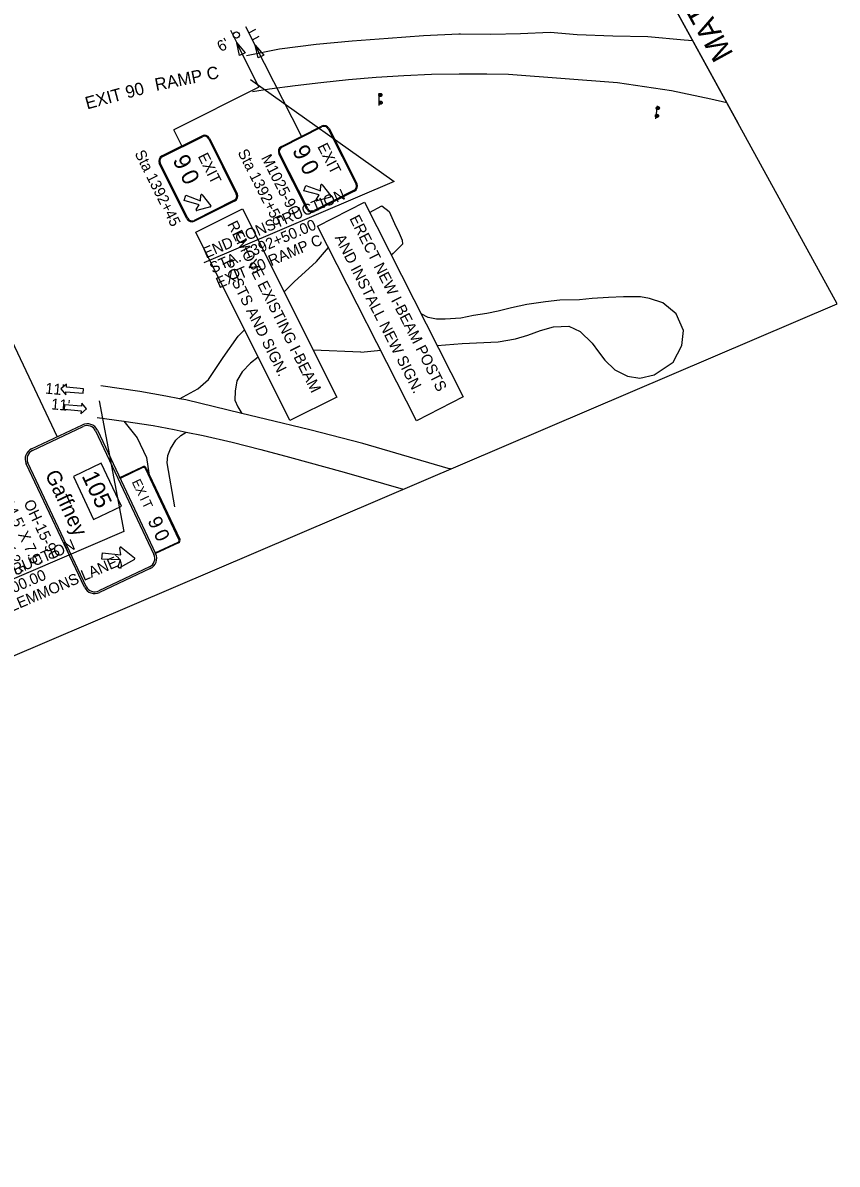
# Model space of a CAD drawing. Extents: x 1786955 to 1788674, y 1181944 to 1183335.
# Drawn here: x 1788151 to 1788674, y 1181944 to 1182676 of the extents above; entities that cross this region are included whole.
import ezdxf

# ---------------------------------------------------------------- set-up
doc = ezdxf.new("R2010")
doc.units = 0
for name, color, linetype in [('RD_EX_Road', 7, 'Continuous'), ('RD_PD_Final_LnLine', 7, 'Continuous'), ('RD_PD_Final_TX', 7, 'Continuous'), ('RD_SHT_MatchLine', 7, 'Continuous'), ('RD_SHT_ShtClip', 7, 'Continuous'), ('RD_TX_RoadID', 7, 'Continuous'), ('SN_P_Signs', 7, 'Continuous')]:
    doc.layers.add(name, color=color, linetype=linetype)

# ---------------------------------------------------------------- blocks, each defined once
blk = doc.blocks.new('SARRW2')
at = {"layer": 'RD_PD_Final_LnLine'}
blk.add_lwpolyline([(-12, 1.2), (-12, -1.2), (-2.83, -1.2), (-2.83, -2.83), (0, 0), (-2.83, 2.83), (-2.83, 1.2)], close=True, dxfattribs=at)

msp = doc.modelspace()

# ---------------------------------------------------------------- linework, layer by layer
at = {"layer": 'RD_EX_Road'}
for points in [[(1788294.76, 1182655.02), (1788315.9, 1182659.32), (1788339.4, 1182662.27), (1788362.48, 1182664.45), (1788385.58, 1182666.23), (1788408.27, 1182667.76), (1788430.98, 1182668.89), (1788431.91, 1182668.93), (1788451.42, 1182668.77), (1788470.57, 1182669.15), (1788489.45, 1182669.9), (1788506.9, 1182668.61), (1788529.76, 1182667.55), (1788552.17, 1182667.13), (1788575.33, 1182665.19), (1788580.91, 1182664.65)], [(1788602.87, 1182624.63), (1788592.5, 1182626.99), (1788567.37, 1182632.3), (1788532.65, 1182637.51), (1788462.82, 1182642.76), (1788448.94, 1182643.08), (1788431.15, 1182643.12), (1788413.36, 1182642.78), (1788395.59, 1182642.04), (1788377.83, 1182640.9), (1788360.11, 1182639.37), (1788342.42, 1182637.45), (1788325.9, 1182635.62), (1788309.42, 1182633.39), (1788298.64, 1182631.68)], [(1788373.65, 1182554.42), (1788381.55, 1182558.7), (1788386.15, 1182555.09), (1788389.74, 1182547.23), (1788392.6, 1182541.2), (1788394.62, 1182536.61), (1788394.77, 1182534.13), (1788388.76, 1182528.14), (1788387.6, 1182526.96)], [(1788318.89, 1182503.49), (1788325.33, 1182509.81), (1788339.58, 1182522.89), (1788347.43, 1182531.8)], [(1788417, 1182469.07), (1788433.11, 1182470.27), (1788456.25, 1182471.37), (1788467.37, 1182473.39), (1788475.12, 1182475.6), (1788483.32, 1182478.73), (1788491.72, 1182480.94), (1788501.54, 1182481.47), (1788508.68, 1182478.12), (1788516.34, 1182470.51), (1788520.52, 1182464.99), (1788524.48, 1182459.64), (1788530.91, 1182453.4), (1788539.19, 1182449.45), (1788547, 1182448.11), (1788556.13, 1182450.18), (1788568.3, 1182458.45), (1788574, 1182469.06), (1788575.05, 1182478.6), (1788570.41, 1182489.42), (1788561.73, 1182496.5), (1788553.15, 1182499.13), (1788547.45, 1182500.29), (1788536.58, 1182500.34), (1788527.01, 1182499.89), (1788516.38, 1182499.14), (1788508.28, 1182498.39), (1788495.71, 1182498.03), (1788486.45, 1182497.14), (1788474.59, 1182495.26), (1788464.73, 1182493.22), (1788456.24, 1182491.16), (1788448.88, 1182489.64), (1788440.29, 1182488.23), (1788432.15, 1182486.61), (1788422.07, 1182485.89), (1788416.53, 1182485.88), (1788411.21, 1182486.96), (1788406.67, 1182489.4)], [(1788251.81, 1182434.94), (1788263.64, 1182441.16), (1788270.3, 1182447.22), (1788279.89, 1182461.34), (1788289.38, 1182475.08), (1788293.54, 1182479.02)], [(1788302.24, 1182461.59), (1788297.39, 1182457.68), (1788291.96, 1182452.16), (1788288.58, 1182446.33), (1788287.41, 1182439.79), (1788287.23, 1182434.08), (1788289.13, 1182429.7), (1788291.78, 1182425.48)], [(1788368.03, 1182464.82), (1788337.6, 1182466.04)], [(1788368.03, 1182464.82), (1788380.85, 1182466.01)], [(1788425.51, 1182389.86), (1788424.18, 1182390.25), (1788369.44, 1182406.17), (1788335.35, 1182414.95), (1788307.01, 1182421.8), (1788291.78, 1182425.48), (1788255.75, 1182434.17), (1788251.81, 1182434.94), (1788242.95, 1182436.66), (1788226.43, 1182439.52), (1788201.38, 1182443.24)], [(1788198.97, 1182422.96), (1788216.07, 1182420.44), (1788234.94, 1182417.66), (1788248.41, 1182415.12), (1788256.03, 1182413.54), (1788267.02, 1182411.26), (1788285.54, 1182407.02), (1788303.98, 1182402.4), (1788322.31, 1182397.39), (1788357.39, 1182387.74), (1788395.25, 1182376.93)], [(1788216.07, 1182420.44), (1788224.66, 1182409.91), (1788230.53, 1182397.22), (1788232.07, 1182387.1)], [(1788248.9, 1182365.67), (1788243.9, 1182393.83), (1788244.22, 1182398.41), (1788245.93, 1182402.83), (1788249.39, 1182408.32), (1788252.66, 1182411.25), (1788256.03, 1182413.54)]]:
    msp.add_lwpolyline(points, dxfattribs=at)
at = {"layer": 'RD_PD_Final_TX'}
for p, q in [((1788297.3, 1182639.75), (1788389.38, 1182574.31)), ((1788389.38, 1182574.31), (1788267.3, 1182522.14)), ((1788200.24, 1182433.67), (1788216.18, 1182349.73)), ((1788216.18, 1182349.73), (1788094.11, 1182297.56))]:
    msp.add_line(p, q, dxfattribs=at)
at = {"layer": 'RD_SHT_MatchLine'}
msp.add_lwpolyline([(1788610.29, 1182611.12), (1788482.57, 1182843.8), (1788373.62, 1183042.27)], dxfattribs=at)
at = {"layer": 'RD_SHT_ShtClip'}
msp.add_lwpolyline([(1788602.87, 1182624.64), (1788373.62, 1183042.27), (1788169.17, 1183137.08), (1788110.36, 1183228.48), (1786954.94, 1182732.25), (1787147.48, 1182122.09), (1787221.15, 1182060.45), (1787293.74, 1181944.03), (1787901.65, 1182166), (1788673.56, 1182495.86)], close=True, dxfattribs=at)
at = {"layer": 'SN_P_Signs'}
for p, q in [((1788300.31, 1182661.7), (1788294.4, 1182673.33)), ((1788296.27, 1182669.66), (1788300.72, 1182671.92)), ((1788284.48, 1182671.26), (1788288.5, 1182663.21)), ((1788298.54, 1182665.19), (1788302.99, 1182667.45)), ((1788302.77, 1182634.64), (1788288.5, 1182663.21)), ((1788329.99, 1182603.26), (1788300.31, 1182661.7)), ((1788302.77, 1182634.64), (1788248.21, 1182607.38)), ((1788379.88, 1182622.96), (1788379.91, 1182630.78)), ((1788379.91, 1182630.41), (1788381.32, 1182629)), ((1788379.91, 1182629), (1788381.32, 1182630.41)), ((1788380.03, 1182625.51), (1788381.44, 1182624.1)), ((1788380.03, 1182624.1), (1788381.44, 1182625.51)), ((1788557.37, 1182614.44), (1788558.38, 1182622.69)), ((1788557.84, 1182622.01), (1788559.25, 1182620.59)), ((1788557.84, 1182620.59), (1788559.25, 1182622)), ((1788557.25, 1182617.02), (1788558.66, 1182615.6)), ((1788557.25, 1182615.61), (1788558.66, 1182617.02)), ((1788253.35, 1182597.07), (1788248.21, 1182607.38)), ((1788317.15, 1182596.74), (1788342.83, 1182609.78)), ((1788317.43, 1182596.2), (1788343.1, 1182609.25)), ((1788347.14, 1182607.93), (1788365.07, 1182572.62)), ((1788347.67, 1182608.2), (1788365.6, 1182572.89)), ((1788240.47, 1182590.64), (1788266.24, 1182603.51)), ((1788240.74, 1182590.1), (1788266.51, 1182602.97)), ((1788270.53, 1182601.63), (1788288.23, 1182566.2)), ((1788271.07, 1182601.9), (1788288.76, 1182566.47)), ((1788333.51, 1182556.59), (1788315.57, 1182591.9)), ((1788334.04, 1182556.86), (1788316.11, 1182592.17)), ((1788256.56, 1182550.38), (1788238.86, 1182585.81)), ((1788257.09, 1182550.65), (1788239.4, 1182586.08)), ((1788286.88, 1182562.18), (1788261.12, 1182549.31)), ((1788363.75, 1182568.59), (1788338.07, 1182555.55)), ((1788364.02, 1182568.05), (1788338.35, 1182555.01)), ((1788102.41, 1182560.53), (1788173.24, 1182410.52)), ((1788287.15, 1182561.64), (1788261.39, 1182548.77)), ((1788262.23, 1182541.7), (1788292.3, 1182556.72)), ((1788292.3, 1182556.72), (1788352.64, 1182435.93)), ((1788340.39, 1182545.67), (1788370.36, 1182560.9)), ((1788370.36, 1182560.9), (1788433.77, 1182436.06)), ((1788322.56, 1182420.91), (1788262.23, 1182541.7)), ((1788403.8, 1182420.83), (1788340.39, 1182545.67)), ((1788352.64, 1182435.93), (1788322.56, 1182420.91)), ((1788433.77, 1182436.06), (1788403.8, 1182420.83)), ((1788201.51, 1182393.52), (1788183.71, 1182385.11)), ((1788214.53, 1182365.95), (1788201.51, 1182393.52)), ((1788183.71, 1182385.11), (1788196.72, 1182357.55)), ((1788196.72, 1182357.55), (1788214.53, 1182365.95))]:
    msp.add_line(p, q, dxfattribs=at)
for points in [[(1788290.33, 1182654.95), (1788288.5, 1182663.21), (1788294, 1182656.78)], [(1788302.2, 1182653.46), (1788300.31, 1182661.7), (1788305.85, 1182655.32)]]:
    msp.add_lwpolyline(points, close=True, dxfattribs=at)
for points in [[(1788380.62, 1182628.71), (1788380.45, 1182628.72), (1788380.29, 1182628.76), (1788380.14, 1182628.83), (1788380, 1182628.92), (1788379.88, 1182629.04), (1788379.78, 1182629.17), (1788379.7, 1182629.32), (1788379.65, 1182629.48), (1788379.62, 1182629.64), (1788379.62, 1182629.81), (1788379.65, 1182629.97), (1788379.71, 1182630.13), (1788379.79, 1182630.27), (1788379.9, 1182630.4), (1788380.03, 1182630.51), (1788380.17, 1182630.6), (1788380.32, 1182630.66), (1788380.48, 1182630.7), (1788380.62, 1182630.71)], [(1788380.62, 1182630.71), (1788380.78, 1182630.69), (1788380.95, 1182630.65), (1788381.1, 1182630.59), (1788381.24, 1182630.49), (1788381.36, 1182630.38), (1788381.46, 1182630.25), (1788381.54, 1182630.1), (1788381.59, 1182629.94), (1788381.62, 1182629.78), (1788381.61, 1182629.61), (1788381.58, 1182629.44), (1788381.53, 1182629.29), (1788381.44, 1182629.14), (1788381.34, 1182629.01), (1788381.21, 1182628.9), (1788381.07, 1182628.82), (1788380.92, 1182628.75), (1788380.75, 1182628.72), (1788380.62, 1182628.71)], [(1788380.74, 1182623.8), (1788380.57, 1182623.82), (1788380.41, 1182623.86), (1788380.26, 1182623.93), (1788380.12, 1182624.02), (1788380, 1182624.13), (1788379.9, 1182624.27), (1788379.82, 1182624.41), (1788379.77, 1182624.57), (1788379.74, 1182624.74), (1788379.74, 1182624.9), (1788379.77, 1182625.07), (1788379.83, 1182625.23), (1788379.91, 1182625.37), (1788380.02, 1182625.5), (1788380.15, 1182625.61), (1788380.29, 1182625.7), (1788380.44, 1182625.76), (1788380.6, 1182625.8), (1788380.74, 1182625.8)], [(1788380.74, 1182625.8), (1788380.9, 1182625.79), (1788381.07, 1182625.75), (1788381.22, 1182625.68), (1788381.36, 1182625.59), (1788381.48, 1182625.48), (1788381.58, 1182625.34), (1788381.66, 1182625.2), (1788381.71, 1182625.04), (1788381.74, 1182624.87), (1788381.73, 1182624.7), (1788381.7, 1182624.54), (1788381.65, 1182624.38), (1788381.56, 1182624.24), (1788381.46, 1182624.11), (1788381.33, 1182624), (1788381.19, 1182623.91), (1788381.04, 1182623.85), (1788380.87, 1182623.81), (1788380.74, 1182623.8)], [(1788558.54, 1182620.3), (1788558.38, 1182620.31), (1788558.22, 1182620.35), (1788558.06, 1182620.42), (1788557.92, 1182620.51), (1788557.8, 1182620.63), (1788557.7, 1182620.76), (1788557.62, 1182620.91), (1788557.57, 1182621.07), (1788557.55, 1182621.23), (1788557.55, 1182621.4), (1788557.58, 1182621.56), (1788557.64, 1182621.72), (1788557.72, 1182621.87), (1788557.82, 1182621.99), (1788557.95, 1182622.1), (1788558.09, 1182622.19), (1788558.25, 1182622.25), (1788558.41, 1182622.29), (1788558.54, 1182622.3)], [(1788558.54, 1182622.3), (1788558.71, 1182622.29), (1788558.87, 1182622.24), (1788559.02, 1182622.18), (1788559.16, 1182622.08), (1788559.29, 1182621.97), (1788559.39, 1182621.84), (1788559.46, 1182621.69), (1788559.52, 1182621.53), (1788559.54, 1182621.37), (1788559.54, 1182621.2), (1788559.51, 1182621.04), (1788559.45, 1182620.88), (1788559.37, 1182620.73), (1788559.26, 1182620.6), (1788559.14, 1182620.49), (1788558.99, 1182620.41), (1788558.84, 1182620.34), (1788558.68, 1182620.31), (1788558.54, 1182620.3)], [(1788557.96, 1182615.31), (1788557.79, 1182615.32), (1788557.63, 1182615.37), (1788557.48, 1182615.43), (1788557.34, 1182615.53), (1788557.22, 1182615.64), (1788557.12, 1182615.77), (1788557.04, 1182615.92), (1788556.99, 1182616.08), (1788556.96, 1182616.24), (1788556.96, 1182616.41), (1788556.99, 1182616.57), (1788557.05, 1182616.73), (1788557.13, 1182616.88), (1788557.24, 1182617.01), (1788557.37, 1182617.12), (1788557.51, 1182617.2), (1788557.66, 1182617.27), (1788557.82, 1182617.3), (1788557.96, 1182617.31)], [(1788557.96, 1182617.31), (1788558.12, 1182617.3), (1788558.29, 1182617.26), (1788558.44, 1182617.19), (1788558.58, 1182617.1), (1788558.7, 1182616.98), (1788558.8, 1182616.85), (1788558.88, 1182616.7), (1788558.93, 1182616.54), (1788558.96, 1182616.38), (1788558.95, 1182616.21), (1788558.92, 1182616.05), (1788558.87, 1182615.89), (1788558.78, 1182615.74), (1788558.68, 1182615.62), (1788558.55, 1182615.51), (1788558.41, 1182615.42), (1788558.26, 1182615.36), (1788558.09, 1182615.32), (1788557.96, 1182615.31)], [(1788331.61, 1182568.27), (1788332.73, 1182571.69), (1788342.14, 1182568.15)], [(1788342.14, 1182568.15), (1788342.41, 1182571.81)], [(1788343.21, 1182572.06), (1788348.78, 1182564.95)], [(1788254.74, 1182562.07), (1788255.88, 1182565.49), (1788265.27, 1182561.88)], [(1788264.42, 1182559.32), (1788254.74, 1182562.07)], [(1788265.27, 1182561.88), (1788265.56, 1182565.54)], [(1788266.36, 1182565.78), (1788271.89, 1182558.64)], [(1788341.31, 1182565.58), (1788331.61, 1182568.27)], [(1788339.36, 1182562.46), (1788341.31, 1182565.58)], [(1788348.55, 1182564.24), (1788339.86, 1182561.79)], [(1788262.45, 1182556.22), (1788264.42, 1182559.32)], [(1788271.65, 1182557.93), (1788262.95, 1182555.54)], [(1788156.96, 1182402.84), (1788189.51, 1182418.21)], [(1788157.47, 1182401.75), (1788190.03, 1182417.13)], [(1788198.01, 1182414.26), (1788235.42, 1182335.05)], [(1788199.1, 1182414.77), (1788236.5, 1182335.56)], [(1788192.01, 1182314.55), (1788154.61, 1182393.77)], [(1788190.93, 1182314.04), (1788153.52, 1182393.25)], [(1788228.35, 1182390.77), (1788213.7, 1182383.85), (1788213.45, 1182384.39), (1788228.09, 1182391.31)], [(1788251.47, 1182344.62), (1788229.95, 1182390.19)], [(1788230.49, 1182390.45), (1788252.01, 1182344.87)], [(1788236.25, 1182336.1), (1788250.9, 1182343.02)], [(1788251.15, 1182342.48), (1788236.5, 1182335.56), (1788236.25, 1182336.1)], [(1788202.03, 1182332), (1788202.38, 1182336.18), (1788214.15, 1182334.72)], [(1788214.15, 1182334.72), (1788213.47, 1182339.11)], [(1788214.44, 1182339.67), (1788222.91, 1182332.88)], [(1788213.88, 1182331.51), (1788202.03, 1182332)], [(1788212.5, 1182327.28), (1788213.88, 1182331.51)], [(1788222.83, 1182331.89), (1788213.36, 1182326.57)], [(1788232.55, 1182327.06), (1788200, 1182311.69)], [(1788233.07, 1182325.98), (1788200.51, 1182310.6)]]:
    msp.add_lwpolyline(points, dxfattribs=at)
msp.add_circle((1788288.31, 1182668.12), 2, dxfattribs=at)
for centre, radius, start, end in [((1788344.46, 1182606.57), 3.6, 26.92604, 116.92604), ((1788344.46, 1182606.57), 3, 26.92604, 116.92604), ((1788267.85, 1182600.29), 3.6, 26.54272, 116.54272), ((1788267.85, 1182600.29), 3, 26.54272, 116.54272), ((1788318.78, 1182593.53), 3.6, 116.92604, 206.92604), ((1788318.78, 1182593.53), 3, 116.92604, 206.92604), ((1788242.08, 1182587.42), 3.6, 116.54272, 206.54272), ((1788242.08, 1182587.42), 3, 116.54272, 206.54272), ((1788342.86, 1182571.78), 0.45, 38.10394, 175.88814), ((1788362.39, 1182571.26), 3, 296.92604, 26.92604), ((1788362.39, 1182571.26), 3.6, 296.92604, 26.92604), ((1788266.01, 1182565.51), 0.45, 37.72062, 175.50482), ((1788285.54, 1182564.86), 3, 296.54272, 26.54272), ((1788285.54, 1182564.86), 3.6, 296.54272, 26.54272), ((1788339.74, 1182562.23), 0.45, 147.96394, 285.74814), ((1788348.43, 1182564.68), 0.45, 285.74814, 38.10394), ((1788262.83, 1182555.98), 0.45, 147.58062, 285.36482), ((1788271.53, 1182558.37), 0.45, 285.36482, 37.72062), ((1788336.72, 1182558.22), 3.6, 206.92604, 296.92604), ((1788336.72, 1182558.22), 3, 206.92604, 296.92604), ((1788259.78, 1182551.99), 3.6, 206.54272, 296.54272), ((1788259.78, 1182551.99), 3, 206.54272, 296.54272), ((1788192.59, 1182411.7), 7.2, 25.27604, 115.27604), ((1788192.59, 1182411.7), 6, 25.27604, 115.27604), ((1788160.03, 1182396.33), 7.2, 115.27604, 205.27604), ((1788160.03, 1182396.33), 6, 115.27604, 205.27604), ((1788228.86, 1182389.68), 1.8, 25.27604, 115.27604), ((1788228.86, 1182389.68), 1.2, 25.27604, 115.27604), ((1788250.38, 1182344.11), 1.2, 295.27604, 25.27604), ((1788250.38, 1182344.11), 1.8, 295.27604, 25.27604), ((1788214.07, 1182339.21), 0.6, 51.25674, 188.72214), ((1788229.99, 1182332.49), 6, 295.27604, 25.27604), ((1788229.99, 1182332.49), 7.2, 295.27604, 25.27604), ((1788222.53, 1182332.41), 0.6, 299.29544, 51.25674), ((1788213.07, 1182327.1), 0.6, 161.82994, 299.29544), ((1788197.44, 1182317.11), 7.2, 205.27604, 295.27604), ((1788197.44, 1182317.11), 6, 205.27604, 295.27604)]:
    msp.add_arc(centre, radius, start, end, dxfattribs=at)

# ---------------------------------------------------------------- block references
at = {"layer": 'RD_PD_Final_LnLine', "xscale": 1.1999999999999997, "yscale": 1.2}
for p, rotation in [((1788175.72, 1182441.17), 174.9172321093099), ((1788192.21, 1182428.36), -5.082767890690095)]:
    msp.add_blockref('SARRW2', p, dxfattribs=dict(at, rotation=rotation))

# ---------------------------------------------------------------- texts
at = {"layer": 'RD_PD_Final_TX'}
for s, rotation, p in [("6'", 28.66729, (1788278.31, 1182657.14)), ('END CONSTRUCTION', 23.13854, (1788268.8, 1182524.85)), ('STA. 1392+50.00', 23.13854, (1788272.93, 1182515.19)), ('EXIT 90 RAMP C', 23.13854, (1788277.05, 1182505.54)), ("11'", 354.91723, (1788165.45, 1182438.23)), ("11'", 354.91723, (1788169.21, 1182428.15)), ('END CONSTRUCTION', 23.13854, (1788095.6, 1182300.27)), ('S-11-645 (LEMMONS LANE)', 23.13854, (1788103.86, 1182280.95)), ('STA. 1391+00.00', 23.13854, (1788099.73, 1182290.61))]:
    msp.add_text(s, height=7, rotation=rotation, dxfattribs=at).set_placement(p)
at = {"layer": 'RD_SHT_MatchLine'}
msp.add_text('MATCHLINE STA. 1395+00 SEE SHEET NO. SN37', height=14, rotation=118.76354, dxfattribs=at).set_placement((1788607.28, 1182656.08))
at = {"layer": 'RD_TX_RoadID'}
for s, rotation, p in [('RAMP C', 11.45943, (1788236.84, 1182632.31)), ('EXIT 90', 15.16201, (1788192.55, 1182620.41))]:
    msp.add_text(s, height=8, rotation=rotation, dxfattribs=at).set_placement(p)
at = {"layer": 'SN_P_Signs'}
for s, height, rotation, p in [('EXIT', 7, 296.92604, (1788340.05, 1182596.7)), ('Sta 1392+45', 7, 296.5428, (1788222.84, 1182592.33)), ('9', 10.8, 296.54272, (1788247.12, 1182588.07)), ('EXIT', 7, 296.54272, (1788263.37, 1182590.45)), ('Sta 1392+55', 7, 296.92612, (1788288.9, 1182592.93)), ('M1025-90', 7, 296.92612, (1788304, 1182589.47)), ('9', 10.8, 296.92604, (1788323.82, 1182594.21)), ('0', 10.8, 296.92604, (1788328.77, 1182584.47)), ('0', 10.8, 296.54272, (1788252, 1182578.3)), ('REMOVE EXISTING I-BEAM', 6.9998, 296.5428, (1788282.27, 1182546.91)), ('ERECT NEW I-BEAM POSTS', 6.9998, 296.92612, (1788360.61, 1182550.58)), ('AND INSTALL NEW SIGN.', 6.9998, 296.92612, (1788351.16, 1182538.28)), ('POSTS AND SIGN.', 6.9998, 296.5428, (1788279, 1182522.13)), ('Gaffney', 9.6, 295.27604, (1788165.33, 1182386.51)), ('105', 10.8, 295.27604, (1788188.89, 1182385.45)), ('E', 6, 295.27604, (1788221.05, 1182381.64)), ('X', 6, 295.27604, (1788223.25, 1182376.98)), ("EP-7.5' X 2.5'", 7, 295.27612, (1788124.15, 1182370.75)), ('I', 6, 295.27604, (1788226.16, 1182370.82)), ("14.5' X 7.5'", 7, 295.27612, (1788138.39, 1182368.45)), ('OH-15-90', 7, 295.27612, (1788151.65, 1182368.25)), ('T', 6, 295.27604, (1788227.43, 1182368.12)), ('9', 9, 295.27604, (1788231.14, 1182356.75)), ('0', 9, 295.27604, (1788235.03, 1182348.52))]:
    msp.add_text(s, height=height, rotation=rotation, dxfattribs=at).set_placement(p)

doc.saveas('drawing.dxf')
